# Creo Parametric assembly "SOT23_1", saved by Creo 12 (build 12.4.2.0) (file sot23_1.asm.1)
Units: Custom; MM, KILOGRAM, SECS

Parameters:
  PTC_WM_ITERATION = "0"
  PTC_WM_VERSION = "-.0"
  PTC_WM_LIFECYCLE_STATE = "In Work"
  PTC_WM_LIFECYCLE = "MO_CADDocument"
  PTC_WM_CREATED_BY = "Maximilian Roepper (Z0017RMS: MO)"
  PTC_WM_CREATED_ON = "18-Sep-26 11:36:42 AM"
  PTC_WM_MODIFIED_BY = "Maximilian Roepper (Z0017RMS: MO)"
  PTC_WM_MODIFIED_ON = "18-Sep-26 11:36:46 AM"
  PDMLINKNUMBER = "PDM000071455041"
  PTC_WM_NUMBER = "PDM000071455041"

Other parameters: WEIGHT, WEIGHT_FACTOR, WEIGHT_ADD, MC_ERRORS, SUPPLIER

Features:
  1. coordinate system
  2. imported feature
  3. component "SHAPESTRING274_1"
  4. component "PIN036_1"
  5. component "PIN035_1"
  6. component "PIN1_1"
  7. component "CASE_1"

Other named items: DRW_VIEW_ORG, ROUGH-GROB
